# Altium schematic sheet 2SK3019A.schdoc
size 127 x 101 mm
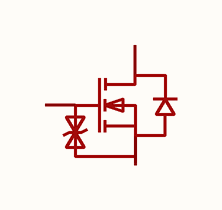
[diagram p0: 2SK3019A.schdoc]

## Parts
Q?  2sk3019a  [SOT-523-3_L1.6-W0.8-P0.50-LS1.6-BR-1]  (value not drawn)

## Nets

Not connected (* = marked no-connect by the designer): Q? 1(G) 2(S) 3(D)

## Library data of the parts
Q? = 2sk3019a: 数量:1个N沟道;漏源电压(Vdss):30V;连续漏极电流(Id):100mA;导通电阻(RDS(on)):3Ω@2.5V;耗散功率(Pd):630mW;阈值电压(Vgs(th)):1.5V;; Manufacturer: CJ(江苏长电/长晶); AddInBom: yes; ModelId: 444e5086b21c45a19e5df515fb74a0e2; ModelTransform: 62.992,62.992,0,90,0,0,0,0,0; Number: 1个N沟道; Drain to Source Voltage: 30V; Current - Continuous Drain(Id): 100mA; Pd - Power Dissipation: 630mW; Gate Threshold Voltage (Vgs(th)): 1.5V; Input Capacitance(Ciss): 30pF; Reverse Transfer Capacitance (Crss@Vds): 4pF; Type: N沟道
